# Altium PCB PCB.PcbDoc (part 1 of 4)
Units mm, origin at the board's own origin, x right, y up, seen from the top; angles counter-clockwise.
Board outline 114 x 86.5 mm, 4 copper layers (TOP, GND, SIG, BOTTOM), stack 1.586 mm thick; 98 components, 195 nets, 719 pads, 522 vias.
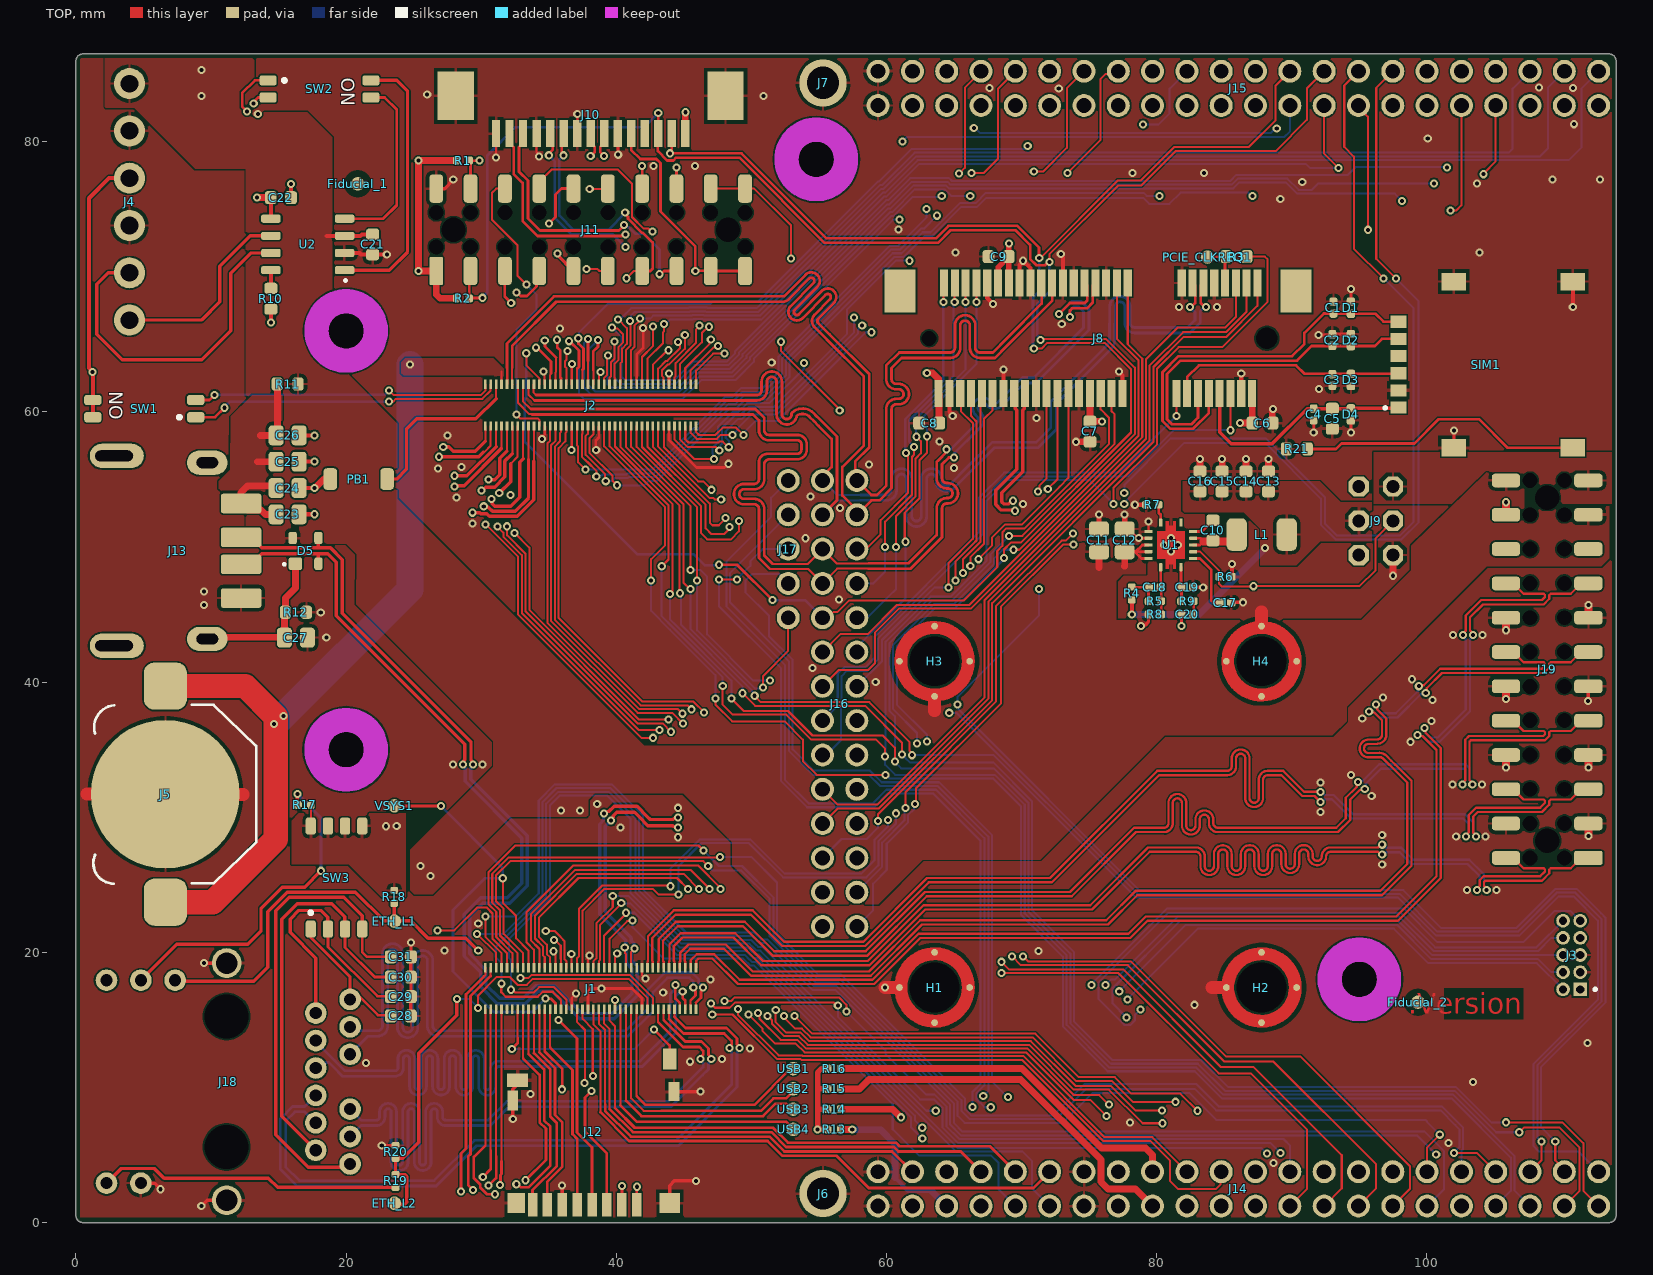
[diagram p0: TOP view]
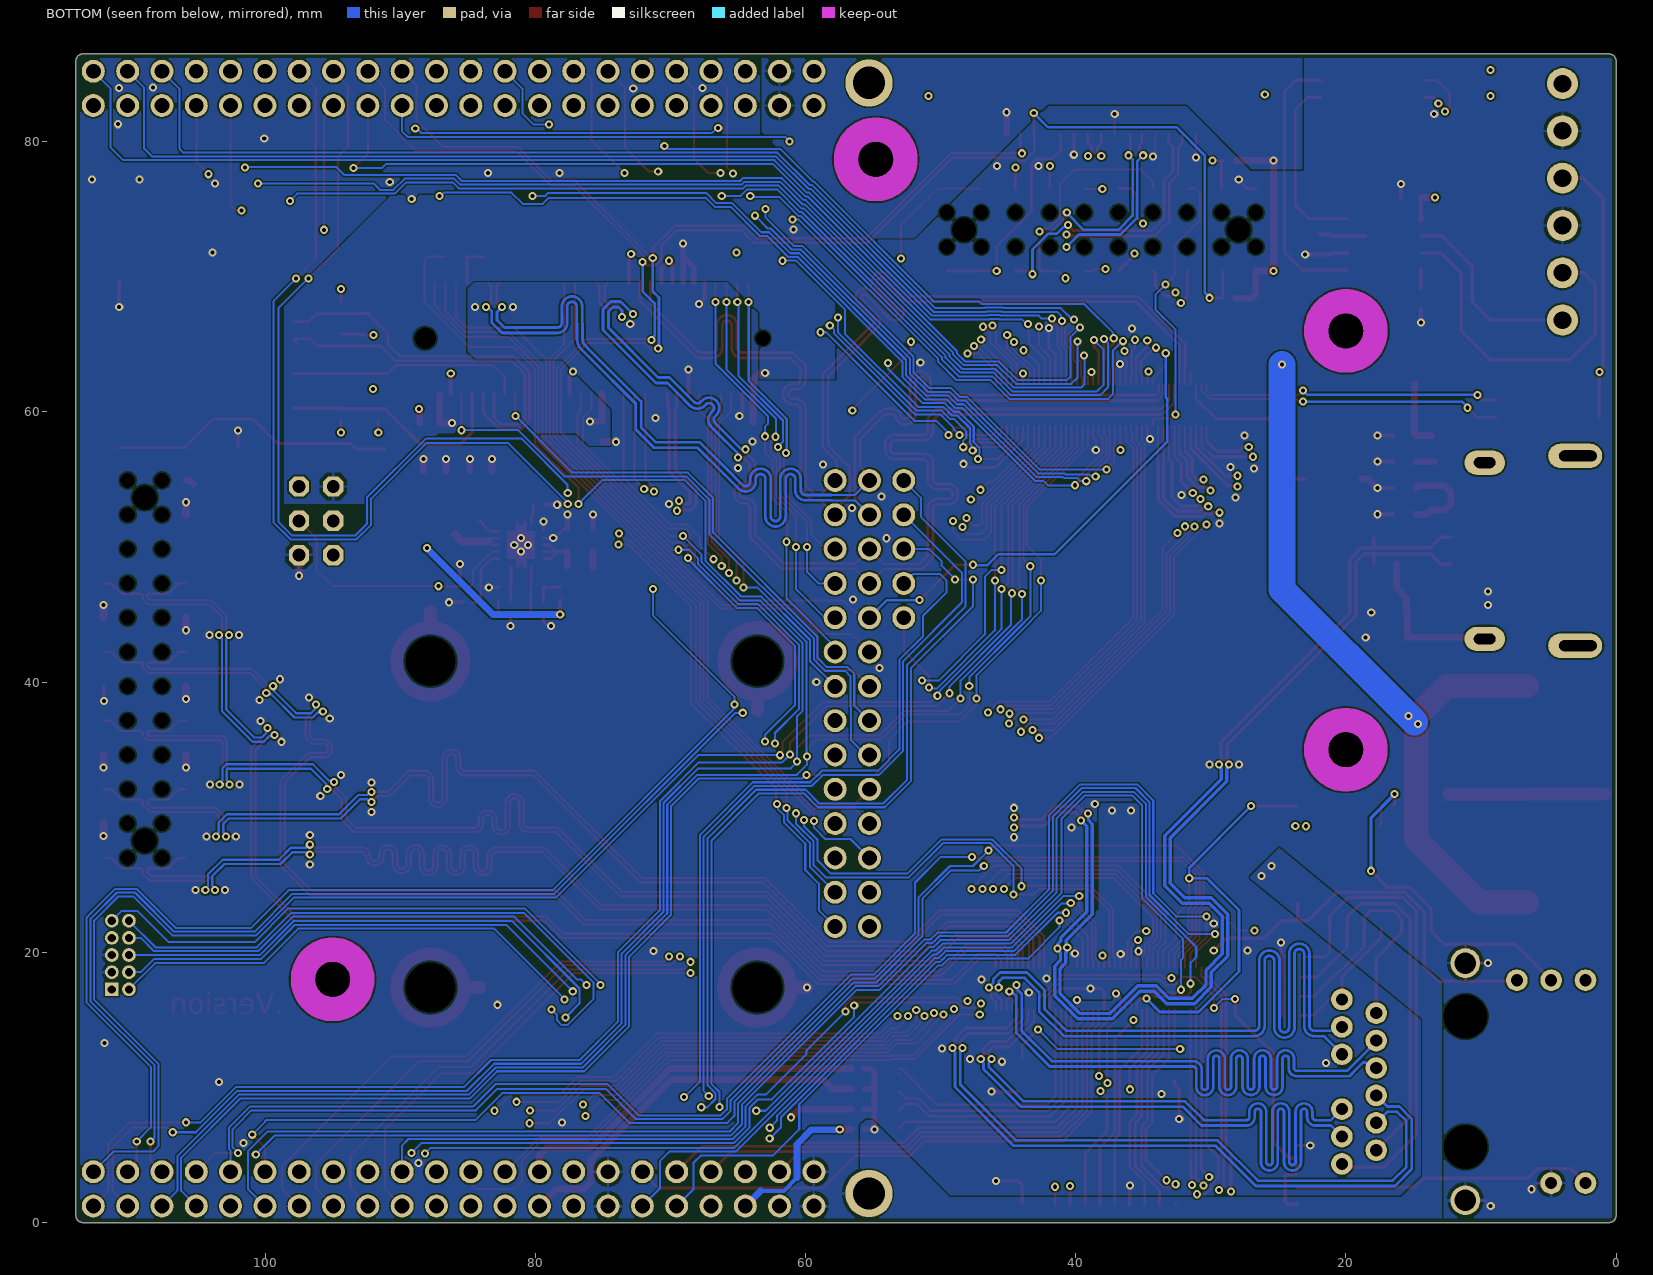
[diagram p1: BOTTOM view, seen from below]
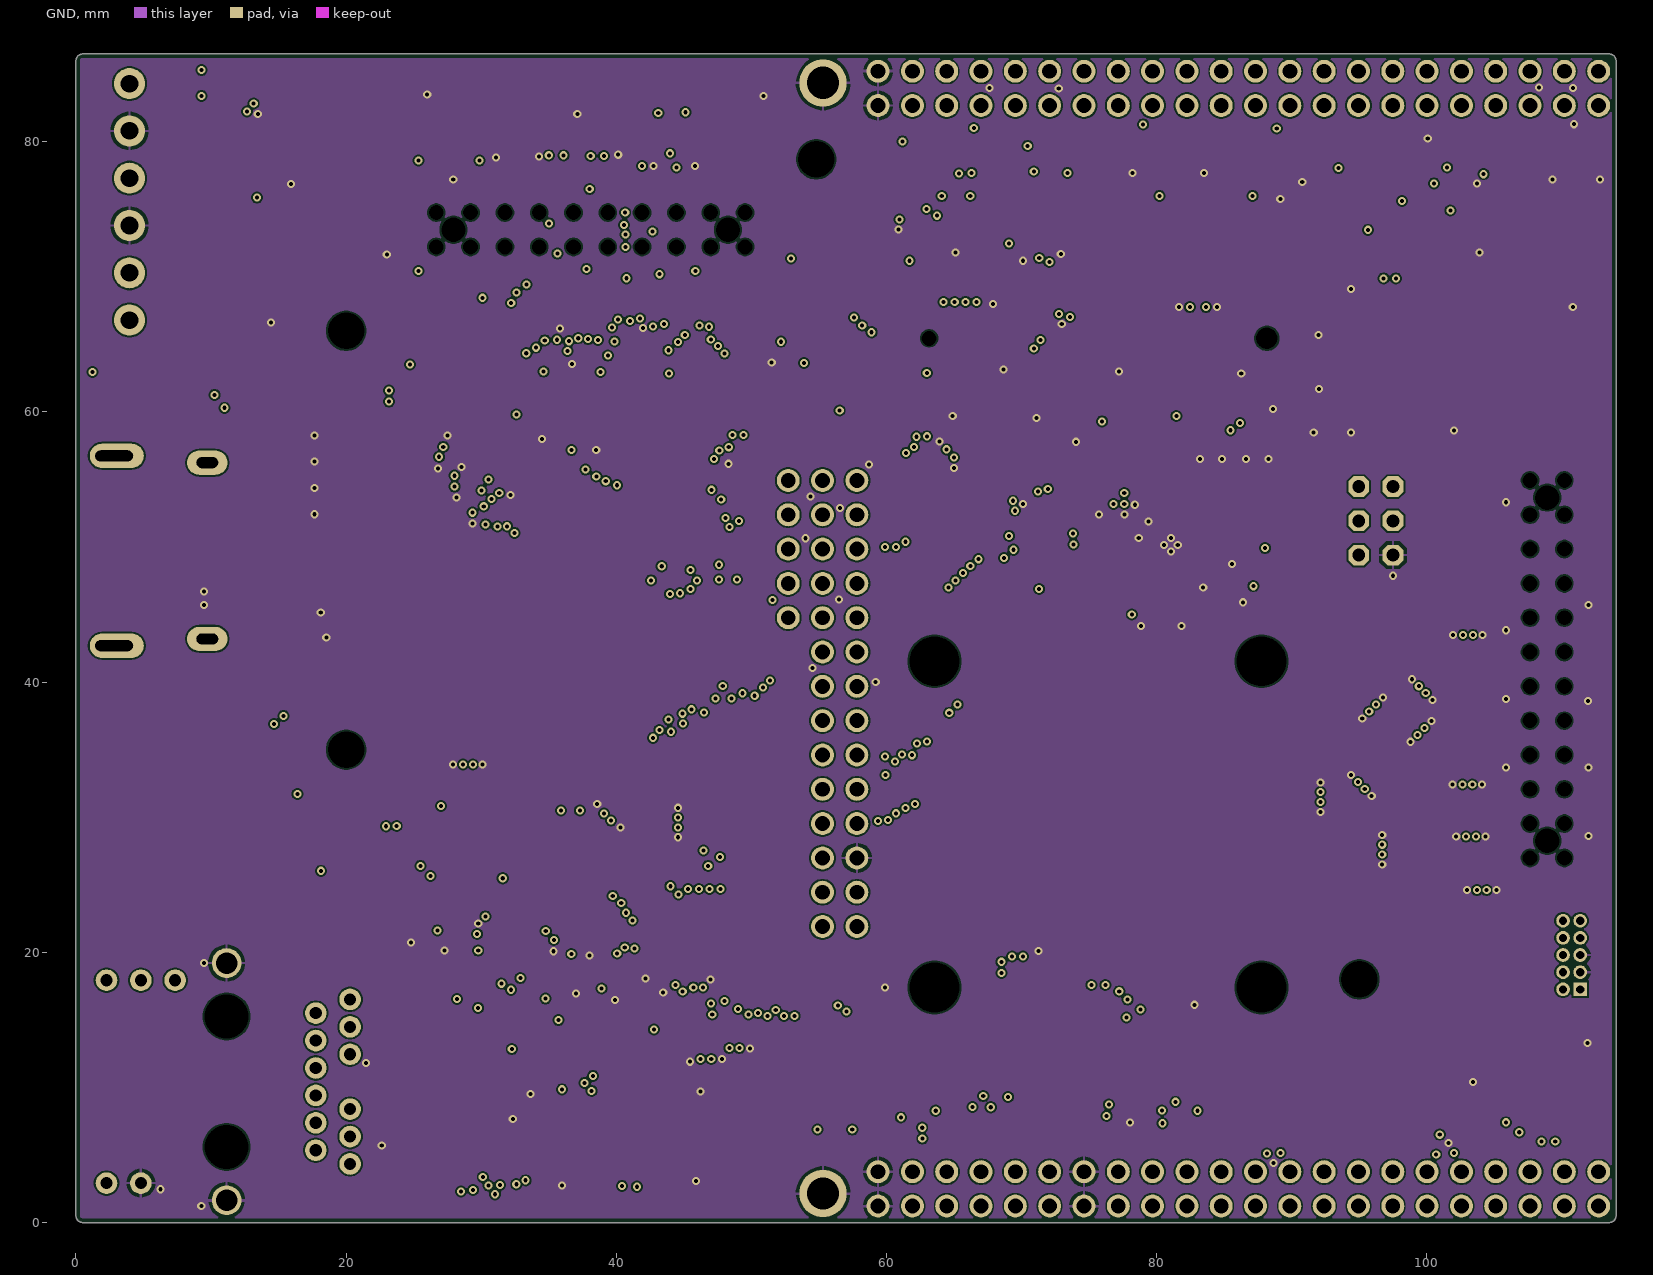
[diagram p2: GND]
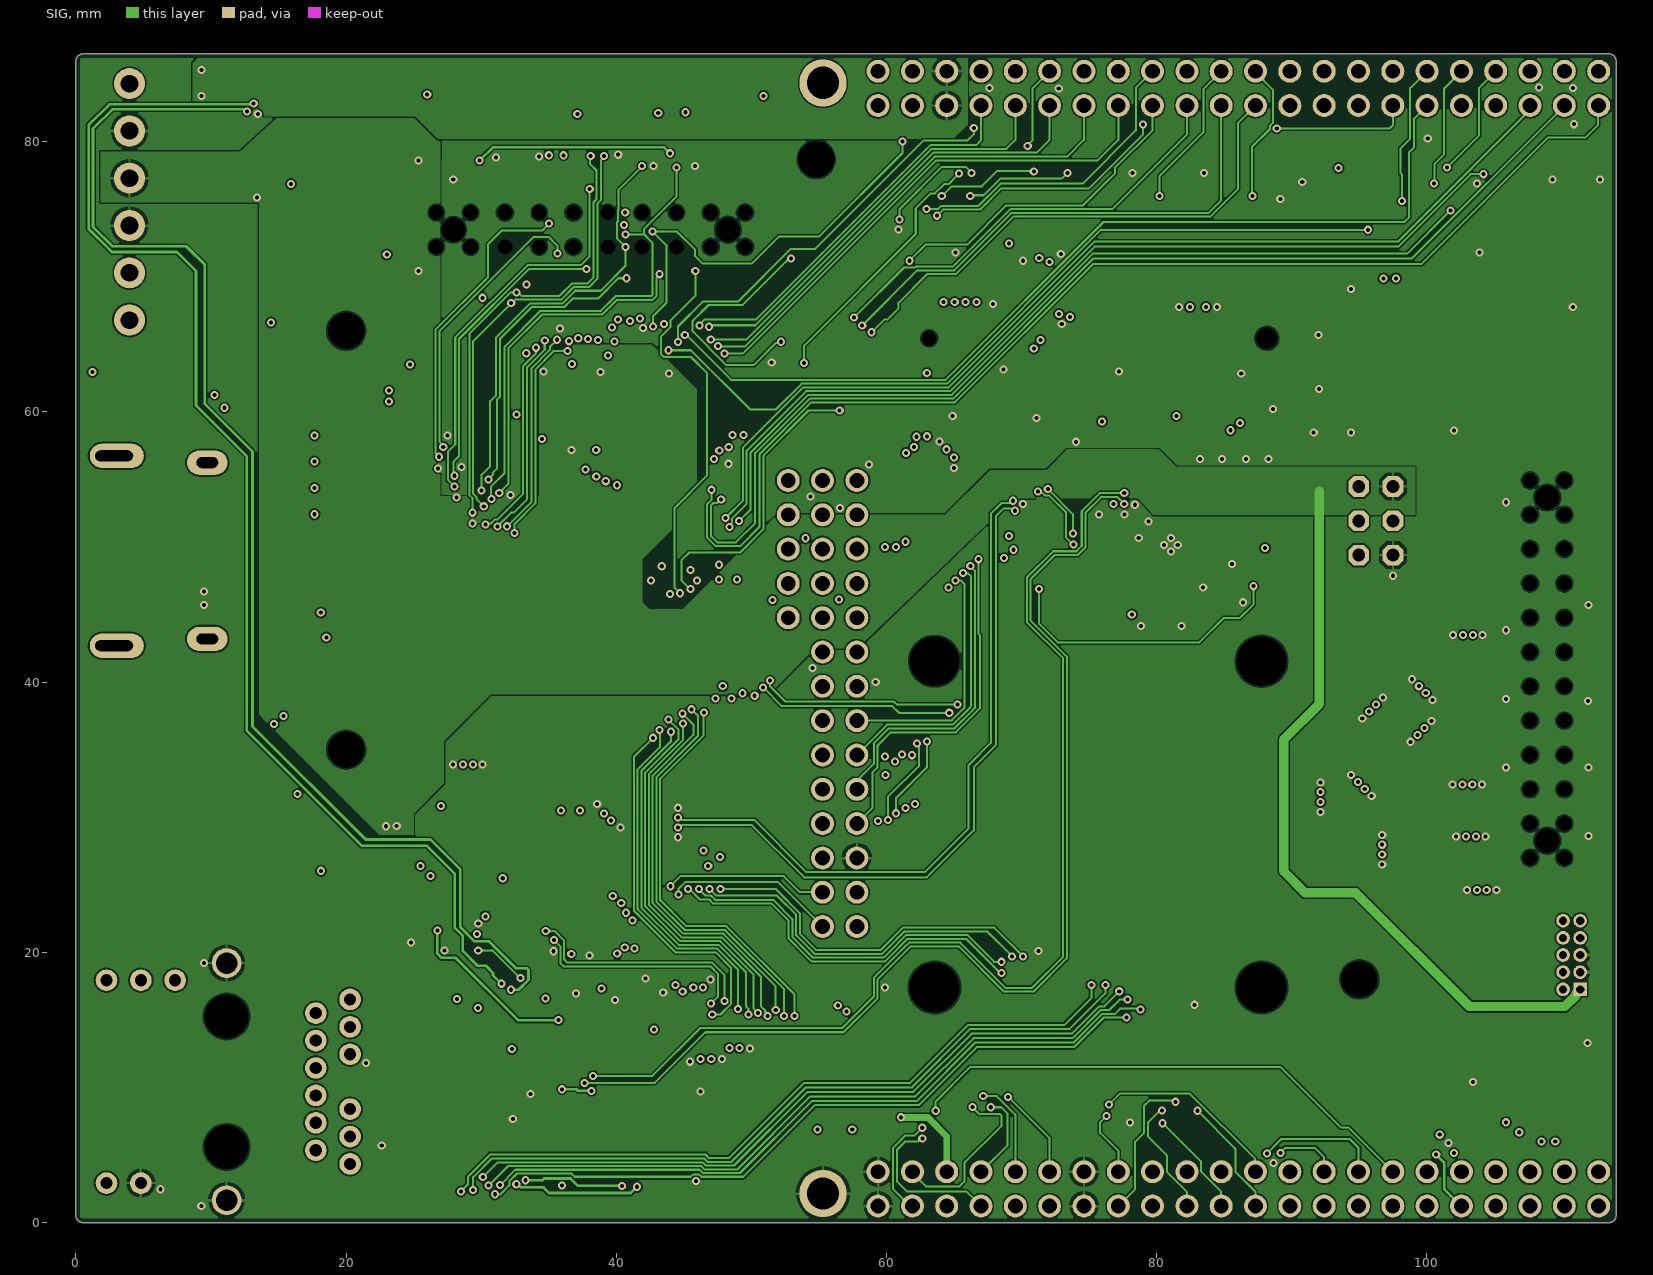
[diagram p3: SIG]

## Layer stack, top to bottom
Top Solder: solder mask 0.01, Solder Resist, Dk 3.5
TOP: signal copper 0.018
Dielectric 1: prepreg 0.14, PP-014, Dk 4.2
GND: signal copper 0.035
Dielectric2: core 1.2, FR-4, Dk 4.8
SIG: signal copper 0.035
Dielectric3: prepreg 0.14, PP-014, Dk 4.2
BOTTOM: signal copper 0.018
Bottom Solder: solder mask 0.01, Solder Resist, Dk 3.5

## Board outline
0.5,0 cw(c0.5,0.5) 0,0.5 0,86 cw(c0.5,86) 0.5,86.5 113.5,86.5 cw(c113.5,86) 114,86 114,0.5 cw(c113.5,0.5) 113.5,0

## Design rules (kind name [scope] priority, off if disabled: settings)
BoardOutlineClearance Silks [(OnLayer('Top Overlay') OR OnLayer('Bottom Overlay'))] p1: gap=0 ignorepadtopadclearanceinfootprint=FALSE
BoardOutlineClearance [All] p2: gap=0.3 ignorepadtopadclearanceinfootprint=FALSE
Clearance [All] p1: gap=0.127 ignorepadtopadclearanceinfootprint=TRUE
Clearance COPPER_0.3mm [All] p2: gap=0.127 ignorepadtopadclearanceinfootprint=TRUE except(0.3: Arc-Fill Arc-Poly Arc-Region Track-Fill Track-Poly Track-Region SMDPad-Fill SMDPad-Poly SMDPad-Region THPad-Fill THPad-Poly THPad-Region Via-Fill Via-Poly Via-Region Fill-Fill Fill-Poly Fill-Region Poly-Poly Poly-Region Region-Region)
Clearance COPPER_0.3mm_DIFF [InNetClass('DIFFERENTIAL')] p3: gap=0.127 ignorepadtopadclearanceinfootprint=TRUE except(0.3: Arc-Fill Arc-Poly Arc-Region Track-Fill Track-Poly Track-Region SMDPad-Fill SMDPad-Poly SMDPad-Region THPad-Fill THPad-Poly THPad-Region Via-Fill Via-Poly Via-Region Fill-Fill Fill-Poly Fill-Region Poly-Poly Poly-Region Region-Region)
Clearance "Generic clearance 0.127mm" [All] p4: gap=0.127 ignorepadtopadclearanceinfootprint=TRUE
ComponentClearance headers [InComponent('J17') vs InComponent('J16')] p1: gap=0 collisioncheckmode=3 verticalgap=0 showdistances=FALSE
ComponentClearance [All] p2: gap=0.2 collisioncheckmode=3 verticalgap=0 showdistances=TRUE
DiffPairsRouting USB [InDifferentialPairClass('USB')] p1: maxlimit=0.254 minlimit=0.15 mostfreqgap=0.254 toplayer_mingap=0.2 toplayer_maxgap=0.2 toplayer_prefgap=0.2 toplayer_minwidth=0.15 toplayer_maxwidth=0.25 toplayer_prefwidth=0.25 midlayer2_mingap=0.24 midlayer2_maxgap=0.24 midlayer2_prefgap=0.24 midlayer2_minwidth=0.15 midlayer2_maxwidth=0.15 midlayer2_prefwidth=0.15 bottomlayer_maxgap=0.15 bottomlayer_prefgap=0.15 bottomlayer_minwidth=0.25 bottomlayer_maxwidth=0.25 bottomlayer_prefwidth=0.25 impedanceprofiledriven=TRUE impedanceprofileid={E6B00C31-4C8E-439C-824F-D2B2CDC26F9C} impedanceprofilevalue=90.000000 maxuncoupledlength=12.7
DiffPairsRouting PCIE [InDifferentialPairClass('PCIE')] p2: maxlimit=0.2 minlimit=0.127 mostfreqgap=0.2 toplayer_mingap=0.2 toplayer_minwidth=0.15 toplayer_maxwidth=0.2 toplayer_prefwidth=0.2 midlayer1_maxgap=0.127 midlayer1_prefgap=0.127 midlayer1_minwidth=0.045 midlayer1_maxwidth=0.045 midlayer1_prefwidth=0.045 midlayer2_maxgap=0.127 midlayer2_prefgap=0.127 midlayer2_minwidth=0.045 midlayer2_maxwidth=0.045 midlayer2_prefwidth=0.045 bottomlayer_mingap=0.2 bottomlayer_minwidth=0.15 bottomlayer_maxwidth=0.2 bottomlayer_prefwidth=0.2 impedanceprofiledriven=TRUE impedanceprofileid={433C8B95-C78D-45E1-AD7A-F8BB8C5C9D6E} impedanceprofilevalue=100.000000 maxuncoupledlength=12.7
DiffPairsRouting DSI [InDifferentialPairClass('DSI')] p3: maxlimit=0.254 minlimit=0.15 mostfreqgap=0.254 toplayer_maxgap=0.15 toplayer_prefgap=0.15 toplayer_minwidth=0.17 toplayer_maxwidth=0.17 toplayer_prefwidth=0.17 bottomlayer_maxgap=0.15 bottomlayer_prefgap=0.15 bottomlayer_minwidth=0.17 bottomlayer_maxwidth=0.17 bottomlayer_prefwidth=0.17 impedanceprofiledriven=TRUE impedanceprofileid={B360A82F-7846-4579-ACC9-A6219EC6DBAC} impedanceprofilevalue=100.000000 maxuncoupledlength=12.7
DiffPairsRouting ETH [InDifferentialPairClass('ETH')] p4: maxlimit=0.2 minlimit=0.127 mostfreqgap=0.2 toplayer_mingap=0.2 toplayer_minwidth=0.15 toplayer_maxwidth=0.2 toplayer_prefwidth=0.2 midlayer1_maxgap=0.127 midlayer1_prefgap=0.127 midlayer1_minwidth=0.045 midlayer1_maxwidth=0.045 midlayer1_prefwidth=0.045 midlayer2_maxgap=0.127 midlayer2_prefgap=0.127 midlayer2_minwidth=0.045 midlayer2_maxwidth=0.045 midlayer2_prefwidth=0.045 bottomlayer_mingap=0.2 bottomlayer_minwidth=0.2 bottomlayer_maxwidth=0.2 bottomlayer_prefwidth=0.2 impedanceprofiledriven=TRUE impedanceprofileid={433C8B95-C78D-45E1-AD7A-F8BB8C5C9D6E} impedanceprofilevalue=100.000000 maxuncoupledlength=12.7
Height [All] p1: minheight=0 maxheight=30 prefheight=12.7
HoleSize [All] p1: absolutevalues=TRUE maxlimit=30 minlimit=0.3 maxpercent=80.000 minpercent=20.000
HoleToHoleClearance [All] p1: gap=0.25 allowstackedmicrovias=FALSE
MatchedLengths MatchedLengths_PCIE [InDifferentialPairClass('PCIE')] p1: tolerance=1.5 checknetsindiffpair=FALSE checkdiffpairvsdiffpair=TRUE checkxsignals=TRUE checkothers=TRUE usedelayunits=TRUE delaytolerance=30.000000
MatchedLengths MatchedLengths_ETH [InDifferentialPairClass('ETH')] p2: tolerance=1.5 checknetsindiffpair=FALSE checkdiffpairvsdiffpair=TRUE checkxsignals=TRUE checkothers=TRUE usedelayunits=TRUE delaytolerance=100.000000
MatchedLengths MatchedLengths_DSI [InDifferentialPairClass('DSI')] p3: tolerance=1.5 checknetsindiffpair=FALSE checkdiffpairvsdiffpair=TRUE checkxsignals=TRUE checkothers=TRUE usedelayunits=TRUE delaytolerance=30.000000
MinimumAnnularRing [All] p1: minimumring=0.15
PlaneConnect [All] p1: pad.planeconnectstyle=Relief pad.reliefexpansion=0.508 pad.reliefentries=4 pad.reliefconductorwidth=0.254 pad.reliefairgap=0.254 via.planeconnectstyle=Direct via.reliefexpansion=0.508 via.reliefentries=4 via.reliefconductorwidth=0.254 via.reliefairgap=0.254
PolygonConnect [All] p1: thpad.connectstyle=Relief thpad.reliefconductorwidth=0.2 thpad.reliefentries=4 thpad.polygonreliefangle="90 Angle" thpad.airgapwidth=0.254 smdpad.connectstyle=Relief smdpad.reliefconductorwidth=0.2 smdpad.reliefentries=4 smdpad.polygonreliefangle="90 Angle" smdpad.airgapwidth=0.254 via.connectstyle=Direct via.reliefconductorwidth=0.254 via.reliefentries=4 via.polygonreliefangle="90 Angle" via.airgapwidth=0.254
RoomDefinition TOP [InComponentClass('TOP')] p1: confinementstyle=ConfineIn formatcopy=TRUE lockcomponents=FALSE outline 121.82,0.96 177.7,0.96 177.7,16.2 121.82,16.2
RoutingVias StandardVias [All] p1: holewidth=0.3 width=0.6 viastyle="Through Hole" minholewidth=0.3 minwidth=0.6 maxholewidth=0.3 maxwidth=0.6
SMDToCorner [All] p1: distance=39370
SilkToSilkClearance [All] p1: silktosilkclearance=0.2
SilkToSolderMaskClearance [IsPad] p1: minsilkscreentomaskgap=0.15 clearancetoexposedcopper=TRUE
SolderMaskExpansion VIAtented [IsVia] p1: expansion=0.102 istentingtop=TRUE
SolderMaskExpansion [All] p2: expansion=0.05 istentingtop=FALSE
UnRoutedNet [All] p1: checkbadconnections=TRUE
ViasUnderSMD Buck_VIA [(ObjectKind = 'Pad') And (PadShape_AllLayers = 'Custom Shape') And (AsMM(PadXSize_AllLayers) = 3.5) And (AsMM(PadYSize_AllLayers) = 2.05)] p1: allowed=TRUE
ViasUnderSMD [All] p2: allowed=FALSE
Width StandardTraces [All] p1: maxlimit=5 minlimit=0.15 preferedwidth=0.15 minimp=50.000000 maximp=50.000000 favimp=50.000000
21 further rules are at their usual default settings.

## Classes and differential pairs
net class DIFFERENTIAL: CAM.CK_1_N CAM.CK_1_P CAM.D0_1_N CAM.D0_1_P CAM.D1_1_N CAM.D1_1_P CAM.D2_1_N CAM.D2_1_P CAM.D3_1_N CAM.D3_1_P CD CLK CMD D0 D1 D2 D3 DSI_CK_N DSI_CK_P DSI_D0_N DSI_D0_P DSI_D1_N DSI_D1_P DSI_D2_N DSI_D2_P DSI_D3_N DSI_D3_P ETH_A_N ETH_A_P ETH_B_N ETH_B_P ETH_C_N ETH_C_P ETH_D_N ETH_D_P mPCIe_CK_N mPCIe_CK_P mPCIe_RX_N mPCIe_RX_P mPCIe_TX_N mPCIe_TX_P USB0_D_N USB0_D_P USB1_D_N USB1_D_P
differential pair class DSI: DSI_CK DSI_D0 DSI_D1 DSI_D2 DSI_D3
differential pair class CAMERA: CAM.CK_1 CAM.D0_1 CAM.D1_1 CAM.D2_1 CAM.D3_1
component class U_USB: C23 C24 C25 C26 C27 D5 J13 R11 R12
differential pair class USB: USB0_D USB1.D_1 USB1_D
differential pair class PCIE: mPCIe_CK mPCIe_RX mPCIe_TX
differential pair class ETH: ETH_A ETH_B ETH_C ETH_D
net class SD: CD CLK CMD D0 D1 D2 D3
net class CAM: CAM.CK_1_N CAM.CK_1_P CAM.D0_1_N CAM.D0_1_P CAM.D1_1_N CAM.D1_1_P CAM.D2_1_P CAM.D3_1_P
component class U_SDcard: J12
component class U_MINI_PCIE: C1 C2 C3 C4 C5 C6 C7 C8 C9 C10 C11 C12 C13 C14 C15 C16 C17 C18 C19 C20 D1 D2 D3 D4 H1 H2 H3 H4 J8 J9 J16 J17 L1 PCIE_CLKREQ1 R3 R4 R5 R6 R7 R8 R9 R21 SIM1 U1
component class U_HEADERS: J14 J15 R13 R14 R15 R16
component class U_ETH: C28 C29 C30 C31 ETH_L1 ETH_L2 J18 R17 R18 R19 R20 SW3
component class U_DSI: J19
component class U_CAN_PHY: C21 C22 R10 U2
component class U_CAMERA: J10 J11
component class TOP: Fiducial_1 Fiducial_2 J3 J4 J5 J6 J7 PB1 R1 R2 SW1 SW2 USB1 USB2 USB3 USB4 VSYS1
component class "HDConnectors FEMALE": J1 J2
differential pair CAM.D3_1: +CAM.D3_1_P -CAM.D3_1_N
differential pair CAM.D2_1: +CAM.D2_1_P -CAM.D2_1_N
differential pair USB1_D: +USB1_D_P -USB1_D_N
differential pair mPCIe_RX: +mPCIe_RX_P -mPCIe_RX_N
differential pair mPCIe_CK: +mPCIe_CK_P -mPCIe_CK_N
differential pair DSI_D3: +DSI_D3_P -DSI_D3_N
differential pair DSI_D2: +DSI_D2_P -DSI_D2_N
differential pair DSI_D1: +DSI_D1_P -DSI_D1_N
differential pair DSI_D0: +DSI_D0_P -DSI_D0_N
differential pair DSI_CK: +DSI_CK_P -DSI_CK_N
differential pair CAM.D1_1: +CAM.D1_1_P -CAM.D1_1_N
differential pair CAM.D0_1: +CAM.D0_1_P -CAM.D0_1_N
differential pair CAM.CK_1: +CAM.CK_1_P -CAM.CK_1_N
differential pair USB0_D: +USB0_D_P -USB0_D_N
differential pair mPCIe_TX: +mPCIe_TX_P -mPCIe_TX_N
differential pair ETH_D: +ETH_D_P -ETH_D_N
differential pair ETH_C: +ETH_C_P -ETH_C_N
differential pair ETH_B: +ETH_B_P -ETH_B_N
differential pair ETH_A: +ETH_A_P -ETH_A_N

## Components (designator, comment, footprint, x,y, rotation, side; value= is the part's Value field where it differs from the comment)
C1 "CC0402JRNPO8BN470" CAP-0402 93.083,67.721 r270 top value=47pF
C2 "CC0402JRNPO8BN470" CAP-0402 93,65.321 r270 top value=47pF
C3 "CC0402JRNPO8BN470" CAP-0402 93,62.368 r90 top value=47pF
C4 "CC0402JRNPO8BN470" CAP-0402 91.622,59.815 r90 top value=47pF
C5 "0603B104K500CT" CAP-0603 93,59.5 r90 top value=100nF
C6 "GRM188R60J476ME15D" CAP-0603 87.826,59.176 r180 top value=47µF
C7 "GRM188R60J476ME15D" CAP-0603 75.056,58.554 r90 top value=47µF
C8 "GRM188R60J476ME15D" CAP-0603 63.156,59.176 r0 top value=47µF
C9 "0603B104K500CT" CAP-0603 68.296,71.5 r180 top value=100nF
C10 "0603B104K500CT" CAP-0603 84.163,51.234 r270 top value=100nF
C11 "CL21A226MAQNNNE" CAP-0805 75.724,50.491 r270 top value=22µF
C12 "CL21A226MAQNNNE" CAP-0805 77.627,50.491 r270 top value=22µF
C13 "GRM188R60J476ME15D" CAP-0603 88.275,54.86 r270 top value=47µF
C14 "GRM188R60J476ME15D" CAP-0603 86.608,54.86 r270 top value=47µF
C15 "GRM188R60J476ME15D" CAP-0603 84.842,54.86 r270 top value=47µF
C16 "GRM188R60J476ME15D" CAP-0603 83.205,54.86 r270 top value=47µF
C17 "C1005B103K500NT" CAP-0402 85.09,45.895 r0 top value=10nF
C18 "GRM1555C1H151FA01D" CAP-0402 79.864,47.025 r180 top value=150pF
C19 "C1005B103K500NT" CAP-0402 82.269,47.025 r180 top value=10nF
C20 "C1005B103K500NT" CAP-0402 82.269,45.013 r0 top value=10nF
C21 "0603B104K500CT" CAP-0603 21.964,72.4 r270 top value=100nF
C22 "0603B104K500CT" CAP-0603 15.167,75.866 r0 top value=100nF
C23 "CL21A226MAQNNNE" CAP-0805 15.664,52.418 r180 top value=22µF
C24 "CL21A226MAQNNNE" CAP-0805 15.664,54.368 r180 top value=22µF
C25 "CL21A226MAQNNNE" CAP-0805 15.664,56.318 r180 top value=22µF
C26 "CL21A226MAQNNNE" CAP-0805 15.664,58.268 r180 top value=22µF
C27 "FV21X472K102ECG" CAP-0805 16.28,43.3 r180 top value=4.7nF
C28 "0603B104K500CT" CAP-0603 24.045,15.288 r0 top value=100nF
C29 "0603B104K500CT" CAP-0603 24.05,16.723 r0 top value=100nF
C30 "0603B104K500CT" CAP-0603 24.045,18.167 r0 top value=100nF
C31 "0603B104K500CT" CAP-0603 24.05,19.669 r0 top value=100nF
D1 "PESD0402-140" 0402 94.376,67.721 r90 top
D2 "PESD0402-140" 0402 94.376,65.321 r90 top
D3 "PESD0402-140" 0402 94.376,62.368 r270 top
D4 "PESD0402-140" 0402 94.376,59.815 r270 top
D5 "PRTR5V0U2X,215" SOT190P230X110-4N 16.993,49.722 r0 top
ETH_L1 "Test point 1.00mm" TP-1.00MM 23.578,22.305 r90 top
ETH_L2 "Test point 1.00mm" TP-1.00MM 23.578,1.425 r180 top
Fiducial_1 "Fiducial mark 1mm with 2mm solder" "Fiducial mark 1mm with circle-Footprint-1" 20.857,76.885 r180 top
Fiducial_2 "Fiducial mark 1mm with 2mm solder" "Fiducial mark 1mm with circle-Footprint-1" 99.334,16.311 r180 top
H1 "9774070151R NO METAL IN HOLE" 9774070151R_HOLE_NO_METAL 63.556,17.397 r0 top
H2 "9774070151R NO METAL IN HOLE" 9774070151R_HOLE_NO_METAL 87.756,17.397 r0 top
H3 "9774070151R NO METAL IN HOLE" 9774070151R_HOLE_NO_METAL 63.556,41.547 r0 top
H4 "9774070151R NO METAL IN HOLE" 9774070151R_HOLE_NO_METAL 87.756,41.547 r0 top
J1 "DF40HC(4.0)-80DS-0.4V(51)-LEFT" DF40HC(4.0)-80DS-0.4V(51) 38.1,17.32 r180 top
J2 "DF40HC(4.0)-80DS-0.4V(51)-RIGHT" DF40HC(4.0)-80DS-0.4V(51) 38.1,60.5 r0 top
J3 "HPH2-A-10-SGA" PINHEAD_2X05_127 110.714,19.8 r180 top
J4 "22TW-277 6 PIN" "22TW-277 6 PIN" 3.962,75.553 r270 top
J5 "3000TR" 3000TR-Footprint-1 6.618,31.712 r90 top
J6 "1502-2" 1502-2 55.3,2.146 r0 top
J7 "1502-2" 1502-2 55.3,84.354 r0 top
J8 "1759546-1" 1759546-1 75.656,65.3 r180 top locked
J9 "PH2-06-UA" 2X03 96.22,51.941 r90 top
J10 "1-84953-5" 1-84952-5-Footprint-1 38.1,83.4 r180 top
J11 "21TW-247" 21TW-247 38.1,73.485 r0 top
J12 "114-00841-68" AMPHENOL_114-00841-68 38.3,7.2 r0 top
J13 "USB-A-S-RA-CS11-SMT-HF-TR" USB-A-S-RA-CS11-SMT-HF-TR 6.222,49.723 r270 top
J14 "61304421121" "PIN HEADER 2.54mm VERT. 2x22POS" 86.044,2.49 r0 top
J15 "61304421121" "PIN HEADER 2.54mm VERT. 2x22POS" 86.044,83.95 r0 top
J16 "PH2-28-UA" PH2-28-UA 56.534,38.419 r270 top
J17 "PH1-05-UA" PH1-05-UA 52.724,49.849 r270 top
J18 "TRJK7003A97NL" "TRJK0071AWNL -Footprint-2" 17.752,10.425 r270 top
J19 "21TW-291" 21TW-291 108.904,40.959 r90 top
L1 "SRP4020TA-3R3M" SRP4020 87.775,50.926 r0 top value=3.3µH
PB1 "IT-1185AP1C-160G-GTR" C&K_PTS820_NO_HOLES-1 20.929,55.035 r0 top
PCIE_CLKREQ1 "Test point 1.00mm" TP-1.00MM 83.759,71.47 r0 top
R1 "RC0402FR-075K1L" RES-0402 28.642,78.612 r180 top value=5.1k
R2 "RC0402FR-075K1L" RES-0402 28.642,68.411 r180 top value=5.1k
R3 "CRCW06030000Z0EAC" RES-0603 85.9,71.5 r180 top value=0
R4 "CRCW040249R9FKEDHP" RES-0402 78.155,46.571 r270 top value=49.9
R5 "CRCW040210K0FKED" RES-0402 79.864,45.994 r180 top value=10k
R6 "RC0402FR-075K1L" RES-0402 85.09,47.8 r180 top value=5.1k
R7 "CRCW040275K0FKED" RES-0402 79.674,53.127 r0 top value=75k
R8 "RC0402FR-073K3L" RES-0402 79.864,45.013 r0 top value=3.3k
R9 "RC0402FR-0734KL" RES-0402 82.269,45.994 r180 top value=34k
R10 "CRCW060375K0FKEAC" RES-0603 14.43,68.381 r90 top value=75k
R11 "CRCW06030000Z0EAC" RES-0603 15.664,62.068 r180 top value=0
R12 "CRCW06031M00FKEA" RES-0603 16.28,45.173 r180 top value=1M
R13 "RC0402FR-073K3L" RES-0402 56.118,6.892 r180 top value=3.3k
R14 "RC0402FR-073K3L" RES-0402 56.118,8.392 r0 top value=3.3k
R15 "RC0402FR-073K3L" RES-0402 56.118,9.892 r180 top value=3.3k
R16 "RC0402FR-073K3L" RES-0402 56.118,11.392 r0 top value=3.3k
R17 "CRCW0402470RJNED" RES-0402 16.92,30.91 r0 top value=470
R18 "CRCW040210K0FKED" RES-0402 23.556,24.102 r90 top value=10k
R19 "CRCW0402470RJNED" RES-0402 23.657,3.079 r90 top value=470
R20 "CRCW040210K0FKED" RES-0402 23.657,5.229 r90 top value=10k
R21 "CRCW06030000Z0EAC" RES-0603 90.376,57.265 r0 top value=0
SIM1 "SIM8060-6-1-14-00-A" SIM8060-6-0-14-00-A-Footprint-1 105.214,63.5 r90 top
SW1 "218-2LPSTRF" CTS-218-2LPST_V 5.055,60.247 r180 top
SW2 "218-2LPSTRF" CTS-218-2LPST_V 18.027,83.909 r0 top
SW3 "218-4LPSTRF" CTS-218-4LPST_V 19.284,25.536 r90 top
U1 "TPS54620RGYR" RHL0014A_V 81.049,50.159 r0 top
U2 "TJA1049T/3J" TJA1049T_3J-Footprint-1 17.157,72.4 r180 top
USB1 "Test point 1.00mm" TP-1.00MM 53.098,11.392 r90 top
USB2 "Test point 1.00mm" TP-1.00MM 53.098,9.892 r90 top
USB3 "Test point 1.00mm" TP-1.00MM 53.098,8.392 r90 top
USB4 "Test point 1.00mm" TP-1.00MM 53.098,6.892 r90 top
VSYS1 "Test point 1.00mm" TP-1.00MM 23.578,30.848 r90 top

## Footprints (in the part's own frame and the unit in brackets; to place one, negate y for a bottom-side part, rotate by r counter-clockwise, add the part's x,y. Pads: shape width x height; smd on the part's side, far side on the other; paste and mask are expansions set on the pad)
1-84952-5-Footprint-1 [mm]
  rect 0.61x2 smd mask+0.05: 1(7,2.8) 2(6,2.8) 3(5,2.8) 4(4,2.8) 5(3,2.8) 6(2,2.8) 7(1,2.8) 8(0,2.8) 9(-1,2.8) 10(-2,2.8) 11(-3,2.8) 12(-4,2.8) 13(-5,2.8) 14(-6,2.8) 15(-7,2.8)
  rect 2.68x3.6 smd mask+0.05: FIX(-9.99,0) FIX(9.99,0)
  body extent -11.46,-3.64 11.46,2.9, height 2.59
2X03 [mm]
  oct 1.501x1.501 / inner oct 1.524x1.524 / far side oct 1.501x1.501 hole 0.95: 1(2.54,1.27) 2(2.54,-1.27) 3(0,1.27) 4(0,-1.27) 5(-2.54,1.27) 6(-2.54,-1.27)
  body extent -3.81,-2.54 3.81,2.5, height 8.5
21TW-247 [mm]
  round 0 hole 1.1 unplated mask+0.2: 0(-11.43,-1.27) 0(-11.43,1.27) 0(-8.89,-1.27) 0(-8.89,1.27) 0(-6.35,-1.27) 0(-6.35,1.27) 0(-3.81,-1.27) 0(-3.81,1.27) 0(-1.27,-1.27) 0(-1.27,1.27) 0(1.27,1.27) 0(1.27,-1.27) 0(3.81,-1.27) 0(3.81,1.27) 0(6.35,-1.27) 0(6.35,1.27) 0(8.89,-1.27) 0(8.89,1.27) 0(11.43,-1.27) 0(11.43,1.27)
  round 0 hole 1.8 unplated paste-2539.97: 0(-10.16,0) 0(10.16,0)
  rrect25% 1.02x2.1 smd mask+0.1: 1(-11.43,-3.05)
  rrect50% 1.02x2.1 smd mask+0.1: 2(-11.43,3.05) 3(-8.89,-3.05) 4(-8.89,3.05) 5(-6.35,-3.05) 6(-6.35,3.05) 7(-3.81,-3.05) 8(-3.81,3.05) 9(-1.27,-3.05) 10(-1.27,3.05) 11(1.27,-3.05) 12(1.27,3.05) 13(3.81,-3.05) 14(3.81,3.05) 15(6.35,-3.05) 16(6.35,3.05) 17(8.89,-3.05) 18(8.89,3.05) 19(11.43,-3.05) 20(11.43,3.05)
  body extent -12.7,-3.29 12.7,3.29, height 3.71
21TW-291 [mm]
  round 0 hole 1.1 unplated mask+0.2: 0(-13.97,-1.27) 0(-13.97,1.27) 0(-11.43,-1.27) 0(-11.43,1.27) 0(-8.89,-1.27) 0(-8.89,1.27) 0(-6.35,-1.27) 0(-6.35,1.27) 0(-3.81,-1.27) 0(-3.81,1.27) 0(-1.27,-1.27) 0(-1.27,1.27) 0(1.27,-1.27) 0(1.27,1.27) 0(3.81,-1.27) 0(3.81,1.27) 0(6.35,-1.27) 0(6.35,1.27) 0(8.89,-1.27) 0(8.89,1.27) 0(11.43,-1.27) 0(11.43,1.27) 0(13.97,-1.27) 0(13.97,1.27)
  round 0 hole 1.8 unplated paste-2539.97: 0(-12.7,0) 0(12.7,0)
  rrect25% 1.02x2.1 smd mask+0.1: 1(-13.97,-3.05)
  rrect50% 1.02x2.1 smd mask+0.1: 2(-13.97,3.05) 3(-11.43,-3.05) 4(-11.43,3.05) 5(-8.89,-3.05) 6(-8.89,3.05) 7(-6.35,-3.05) 8(-6.35,3.05) 9(-3.81,-3.05) 10(-3.81,3.05) 11(-1.27,-3.05) 12(-1.27,3.05) 13(1.27,-3.05) 14(1.27,3.05) 15(3.81,-3.05) 16(3.81,3.05) 17(6.35,-3.05) 18(6.35,3.05) 19(8.89,-3.05) 20(8.89,3.05) 21(11.43,-3.05) 22(11.43,3.05) 23(13.97,-3.05) 24(13.97,3.05)
  body extent -15.27,-3.29 15.21,3.29, height 3.71
"22TW-277 6 PIN" [mm]
  round 2.3 hole 1.3: 1(-8.75,0) 2(-5.25,0) 3(-1.75,0) 4(1.75,0) 5(5.25,0) 6(8.75,0)
  body extent -10.98,-3.75 11,3.25, height 8.31
0402 [mm] "Chip Resistor, 2-Leads, Body  0402 (in) 1005 (mm), IPC Medium Density"
  rrect50% 0.62x0.62 smd mask+0.05: A(0.45,0) C(-0.45,0)
  body extent -0.5,-0.3 0.5,0.3, height 0.5
1502-2 [mm]
  round 3.5 hole 2.4 paste-2539.97 mask+0.102: 1(0,0)
  body extent -1.58,-1.59 1.58,1.59, height 5.63
3000TR-Footprint-1 [mm] "Default PCB Component"
  rrect50% 3.5x3.2 smd paste-0.3: 1(-8,0) 2(8,0)
  round 11 smd paste-3.5: 3(0,0)
  silkscreen extent -6.62,-6.73 6.61,5.33, body extent -9.46,-6.91 9.49,5.15, height 3.2
1759546-1 [mm]
  rect 0.6x2 smd mask+0: 1(-11.8,-4.25) 2(-11.4,3.95) 3(-11,-4.25) 4(-10.6,3.95) 5(-10.2,-4.25) 6(-9.8,3.95) 7(-9.4,-4.25) 8(-9,3.95) 9(-8.6,-4.25) 10(-8.2,3.95) 11(-7.8,-4.25) 12(-7.4,3.95) 13(-7,-4.25) 14(-6.6,3.95) 15(-6.2,-4.25) 16(-5.8,3.95) 17(-2.2,-4.25) 18(-1.8,3.95) 19(-1.4,-4.25) 20(-1,3.95) 21(-0.6,-4.25) 22(-0.2,3.95) 23(0.2,-4.25) 24(0.6,3.95) 25(1,-4.25) 26(1.4,3.95) 27(1.8,-4.25) 28(2.2,3.95) 29(2.6,-4.25) 30(3,3.95) 31(3.4,-4.25) 32(3.8,3.95) 33(4.2,-4.25) 34(4.6,3.95) 35(5,-4.25) 36(5.4,3.95) 37(5.8,-4.25) 38(6.2,3.95) 39(6.6,-4.25) 40(7,3.95) 41(7.4,-4.25) 42(7.8,3.95) 43(8.2,-4.25) 44(8.6,3.95) 45(9,-4.25) 46(9.4,3.95) 47(9.8,-4.25) 48(10.2,3.95) 49(10.6,-4.25) 50(11,3.95) 51(11.4,-4.25) 52(11.8,3.95)
  round 0 hole 1.6 unplated: MH1(-12.5,-0.15)
  round 0 hole 1.1 unplated: MH2(12.5,-0.15)
  rect 2.3x3.2 smd: MP1(-14.65,-3.65) MP2(14.65,-3.65)
  body extent -15,-4.56 15,4.7, height 9.92
9774070151R_HOLE_NO_METAL [mm]
  round 1 hole 3.7 unplated paste-2539.97 mask+0.1: 0(0,0)
  round 0.5 smd paste-10: 1(-2.6,0) 1(0,-2.6) 1(0,2.6) 1(2.6,0)
  TOP circle w0.95: c0,0 r2.5
  TOP pour cut-out: 0,3.3 1.263,3.049 2.333,2.333 3.049,1.263 3.3,0 3.3,0 3.049,-1.263 2.333,-2.333 1.263,-3.049 0,-3.3 0,-3.3 -1.263,-3.049 -2.333,-2.333 -3.049,-1.263 -3.3,0 -3.3,0 -3.049,1.263 -2.333,2.333 -1.263,3.049 0,3.3
AMPHENOL_114-00841-68 [mm]
  rect 0.7x1.75 smd mask+0.05: 1(3.2,-5.888) 2(2.1,-5.888) 3(1,-5.888) 4(-0.1,-5.888) 5(-1.2,-5.888) 6(-2.3,-5.888) 7(-3.4,-5.888) 8(-4.5,-5.888)
  rect 1x1.55 smd mask+0.05: CD1(5.65,4.912)
  rect 1.55x1 smd mask+0.05: CD2(-5.602,3.337)
  rect 1.3x1.5 smd mask+0: SH1(-5.7,-5.76)
  rect 1.5x1.5 smd mask+0: SH2(5.65,-5.76)
  rect 0.8x1.4 smd mask+0.05: SH3(5.975,2.487)
  rect 0.8x1.5 smd mask+0.05: SH4(-5.975,1.837)
  body extent -6,-10.29 6,4.99, height 1.6
C&K_PTS820_NO_HOLES-1 [mm]
  rrect49% 1x1.6 smd mask+0.05: 1(-2.1,0) 2(2.1,0)
  body extent -2.25,-1.45 2.25,1.45, height 2
CAP-0402 [mm] "Chip Capacitor, 2-Leads, Body  0402 (in) 1005 (mm), IPC Medium Density"
  rrect52% 0.63x0.58 smd mask+0.05: 1(-0.435,0) 2(0.435,0)
  body extent -0.5,-0.25 0.5,0.25, height 0.5
CAP-0603 [mm] "Chip Capacitor, Body 0603 imperial,1.6x0.8mm, IPC High Density"
  rrect51% 0.87x0.97 smd mask+0.05: 1(-0.75,0) 2(0.75,0)
  body extent -0.8,-0.4 0.8,0.4, height 0.8
CAP-0805 [mm] "Chip Capacitor, Body 0805 imperial, 2.0x1.2mm, IPC Medium Density"
  rrect45% 1.11x1.47 smd mask+0.05: 1(-0.85,0) 2(0.85,0)
  body extent -1,-0.62 1,0.63, height 1.25
CTS-218-2LPST_V [mm] "SMD, 4-Leads, Body 5.8x3.71mm, Pitch 1.27mm"
  rrect50% 1.27x0.76 smd: 1(-3.81,0.635) 2(-3.81,-0.635) 3(3.81,-0.635) 4(3.81,0.635)
  silkscreen extent -2.7,0.54 -2.5,0.73, body extent -4.22,-1.85 4.22,1.86, height 2.5
CTS-218-4LPST_V [mm] "SMD, 8-Leads, Body 5.8x6.25mm, Pitch 1.27mm"
  rrect50% 1.27x0.76 smd: 1(-3.81,1.905) 2(-3.81,0.635) 3(-3.81,-0.635) 4(-3.81,-1.905) 5(3.81,-1.905) 6(3.81,-0.635) 7(3.81,0.635) 8(3.81,1.905)
  silkscreen extent -2.7,1.81 -2.5,2, body extent -4.22,-3.13 4.22,3.13, height 2.59
DF40HC(4.0)-80DS-0.4V(51) [mm]
  rect 0.2x0.7 smd mask+0: 1(-7.8,1.54) 2(-7.8,-1.54) 3(-7.4,1.54) 4(-7.4,-1.54) 5(-7,1.54) 6(-7,-1.54) 7(-6.6,1.54) 8(-6.6,-1.54) 9(-6.2,1.54) 10(-6.2,-1.54) 11(-5.8,1.54) 12(-5.8,-1.54) 13(-5.4,1.54) 14(-5.4,-1.54) 15(-5,1.54) 16(-5,-1.54) 17(-4.6,1.54) 18(-4.6,-1.54) 19(-4.2,1.54) 20(-4.2,-1.54) 21(-3.8,1.54) 22(-3.8,-1.54) 23(-3.4,1.54) 24(-3.4,-1.54) 25(-3,1.54) 26(-3,-1.54) 27(-2.6,1.54) 28(-2.6,-1.54) 29(-2.2,1.54) 30(-2.2,-1.54) 31(-1.8,1.54) 32(-1.8,-1.54) 33(-1.4,1.54) 34(-1.4,-1.54) 35(-1,1.54) 36(-1,-1.54) 37(-0.6,1.54) 38(-0.6,-1.54) 39(-0.2,1.54) 40(-0.2,-1.54) 41(0.2,1.54) 42(0.2,-1.54) 43(0.6,1.54) 44(0.6,-1.54) 45(1,1.54) 46(1,-1.54) 47(1.4,1.54) 48(1.4,-1.54) 49(1.8,1.54) 50(1.8,-1.54) 51(2.2,1.54) 52(2.2,-1.54) 53(2.6,1.54) 54(2.6,-1.54) 55(3,1.54) 56(3,-1.54) 57(3.4,1.54) 58(3.4,-1.54) 59(3.8,1.54) 60(3.8,-1.54) 61(4.2,1.54) 62(4.2,-1.54) 63(4.6,1.54) 64(4.6,-1.54) 65(5,1.54) 66(5,-1.54) 67(5.4,1.54) 68(5.4,-1.54) 69(5.8,1.54) 70(5.8,-1.54) 71(6.2,1.54) 72(6.2,-1.54) 73(6.6,1.54) 74(6.6,-1.54) 75(7,1.54) 76(7,-1.54) 77(7.4,1.54) 78(7.4,-1.54) 79(7.8,1.54) 80(7.8,-1.54)
  body extent -9.3,-1.69 9.3,1.69, height 3.89
"Fiducial mark 1mm with circle-Footprint-1" [mm]
  round 1 smd paste-10 mask+0.5: 1(0,0)
  TOP pour cut-out: 0,1 0.383,0.924 0.707,0.707 0.924,0.383 1,0 1,0 0.924,-0.383 0.707,-0.707 0.383,-0.924 0,-1 0,-1 -0.383,-0.924 -0.707,-0.707 -0.924,-0.383 -1,0 -1,0 -0.924,0.383 -0.707,0.707 -0.383,0.924 0,1
PH1-05-UA [mm]
  round 1.7 hole 1.1 mask+0.1: 1(-5.08,0) 2(-2.54,0) 3(0,0) 4(2.54,0) 5(5.08,0)
  body extent -6.35,-1.27 6.35,1.27, height 9.5
PH2-28-UA [mm]
  round 1.7 hole 1.1 mask+0.1: 1(-16.51,-1.27) 2(-16.51,1.27) 3(-13.97,-1.27) 4(-13.97,1.27) 5(-11.43,-1.27) 6(-11.43,1.27) 7(-8.89,-1.27) 8(-8.89,1.27) 9(-6.35,-1.27) 10(-6.35,1.27) 11(-3.81,-1.27) 12(-3.81,1.27) 13(-1.27,-1.27) 14(-1.27,1.27) 15(1.27,-1.27) 16(1.27,1.27) 17(3.81,-1.27) 18(3.81,1.27) 19(6.35,-1.27) 20(6.35,1.27) 21(8.89,-1.27) 22(8.89,1.27) 23(11.43,-1.27) 24(11.43,1.27) 25(13.97,-1.27) 26(13.97,1.27) 27(16.51,-1.27) 28(16.51,1.27)
  body extent -17.78,-2.54 17.78,2.54, height 9.5
"PIN HEADER 2.54mm VERT. 2x22POS" [mm]
  round 1.7 hole 1.1 mask+0.1: 1(-26.67,-1.27) 2(-26.67,1.27) 3(-24.13,-1.27) 4(-24.13,1.27) 5(-21.59,-1.27) 6(-21.59,1.27) 7(-19.05,-1.27) 8(-19.05,1.27) 9(-16.51,-1.27) 10(-16.51,1.27) 11(-13.97,-1.27) 12(-13.97,1.27) 13(-11.43,-1.27) 14(-11.43,1.27) 15(-8.89,-1.27) 16(-8.89,1.27) 17(-6.35,-1.27) 18(-6.35,1.27) 19(-3.81,-1.27) 20(-3.81,1.27) 21(-1.27,-1.27) 22(-1.27,1.27) 23(1.27,-1.27) 24(1.27,1.27) 25(3.81,-1.27) 26(3.81,1.27) 27(6.35,-1.27) 28(6.35,1.27) 29(8.89,-1.27) 30(8.89,1.27) 31(11.43,-1.27) 32(11.43,1.27) 33(13.97,-1.27) 34(13.97,1.27) 35(16.51,-1.27) 36(16.51,1.27) 37(19.05,-1.27) 38(19.05,1.27) 39(21.59,-1.27) 40(21.59,1.27) 41(24.13,-1.27) 42(24.13,1.27) 43(26.67,-1.27) 44(26.67,1.27)
  body extent -27.94,-2.54 27.94,2.54, height 9.5
PINHEAD_2X05_127 [mil]
  rect 38.73x38.73 / inner rect 38.74x38.74 / far side rect 38.73x38.73 hole 23.62: 1(-25,100)
  round 40 hole 23.62: 2(25,100) 3(-25,50) 4(25,50) 5(-25,0) 6(25,0) 7(-25,-50) 8(25,-50) 9(-25,-100) 10(25,-100)
  silkscreen extent -70,98 -67,102, body extent -68,-125 68,125, height 158
RES-0402 [mm] "Chip Resistor, 2-Leads, Body  0402 (in) 1005 (mm), IPC Medium Density"
  rrect51% 0.55x0.58 smd mask+0.05: 1(-0.475,0) 2(0.475,0)
  body extent -0.5,-0.25 0.5,0.25, height 0.34
RES-0603 [mm] "Chip Resistor - Body 0603 imperial,1.6x0.8mm, IPC High Density"
  rrect51% 0.82x0.97 smd mask+0.05: 1(-0.775,0) 2(0.775,0)
  body extent -0.8,-0.4 0.8,0.4, height 0.43
RHL0014A_V [mm] "QFN, 14-Leads, Body 3.5x3.5mm, Pitch 0.5mm, Thermal Pad 2.05x2.05mm, TI Recommended"
  rrect42% 0.24x0.6 smd mask+0.05: 1(-0.75,1.65) 7(-0.75,-1.65) 8(0.75,-1.65) 14(0.75,1.65)
  rrect42% 0.6x0.24 smd mask+0.05: 2(-1.65,1) 3(-1.65,0.5) 4(-1.65,0) 5(-1.65,-0.5) 6(-1.65,-1) 9(1.65,-1) 10(1.65,-0.5) 11(1.65,0) 12(1.65,0.5) 13(1.65,1)
  round 0.025 smd paste-2539.97 mask+0.05: 15(0,0)
  TOP region: -0.974,1.025 -0.375,1.025 -0.375,1.75 -0.175,1.75 -0.175,1.425 0.175,1.425 0.175,1.75 0.375,1.75 0.375,1.025 0.974,1.025 0.993,1.021 1.01,1.01 1.021,0.993 1.025,0.974 1.025,0.974 1.025,-0.974 1.021,-0.993 1.01,-1.01 0.993,-1.021 0.974,-1.025 0.974,-1.025 0.375,-1.025 0.375,-1.75 0.175,-1.75 0.175,-1.426 -0.175,-1.425 -0.175,-1.75 -0.375,-1.75 -0.375,-1.025 -0.974,-1.025 -0.994,-1.021 -1.01,-1.01 -1.021,-0.993 -1.025,-0.974 -1.025,-0.974 -1.025,0.974 -1.021,0.993 -1.01,1.01 -0.994,1.021 -0.974,1.025
  body extent -1.68,-1.83 1.68,1.82, height 1
SIM8060-6-0-14-00-A-Footprint-1 [mm]
  rect 0.9x1.2 smd: C1(-3.17,7.32) C2(-0.63,7.32) C3(1.91,7.32) C5(-1.9,7.32) C6(0.64,7.32) C7(3.18,7.32)
  rect 1.3x1.8 smd: G1(-6.15,3.22) G2(6.15,3.22) G3(-6.15,-5.58) G4(6.15,-5.58)
  silkscreen extent -3.3,8.2 -3.1,8.4, body extent -6.67,-7.92 6.67,7.83, height 1.53
SOT190P230X110-4N [mm]
  rrect33% 1.01x0.91 smd paste+0 mask+0.05: 1(-0.75,-0.955)
  rrect49% 0.61x0.91 smd paste+0 mask+0.05: 2(0.95,-0.955) 3(0.95,0.955) 4(-0.95,0.955)
  silkscreen extent -1.62,-1.05 -1.52,-0.95, body extent -1.45,-1.15 1.45,1.15, height 1
SRP4020 [mm]
  rrect50% 1.5x2.4 smd: 1(-1.85,0) 2(1.85,0)
  body extent -2.7,-2.25 2.7,2.25, height 0.25
TJA1049T_3J-Footprint-1 [mm]
  rrect50% 1.45x0.6 smd: 1(-2.725,1.905) 2(-2.725,0.635) 3(-2.725,-0.635) 4(-2.725,-1.905) 5(2.725,-1.905) 6(2.725,-0.635) 7(2.725,0.635) 8(2.725,1.905)
  silkscreen extent -2.84,2.62 -2.74,2.72, body extent -3,-2.5 3,2.5, height 1.75
TP-1.00MM [mm]
  rrect100% 1x1 smd paste-2.54: X(0,0)
"TRJK0071AWNL -Footprint-2" [mm]
  round 1.6 hole 0.9: 1(5.075,0) 2(3.045,0) 3(1.015,0) 4(-1.015,0) 5(-3.045,0) 6(-5.075,0) 7(6.09,2.54) 8(4.06,2.54) 9(2.03,2.54) 10(-2.03,2.54) 11(-4.06,2.54) 12(-6.09,2.54) 13(7.51,-12.95) 14(7.51,-15.49) 15(-7.51,-10.41) 16(-7.51,-12.95) 17(-7.51,-15.49)
  round 2.2 hole 1.6: SH1(-8.78,-6.6) SH2(8.78,-6.6)
  round 0 hole 3.25 unplated: SHNP1(-4.825,-6.6) SHNP2(4.825,-6.6)
  body extent -10.45,-19.78 10.5,4.35, height 12.89
USB-A-S-RA-CS11-SMT-HF-TR [mm]
  rrect25% 1.45x3 smd paste+0 mask+0.05: 1(-3.5,6) 2(-1,6) 3(1,6) 4(3.5,6)
  oval 1.8x3 hole 0.8 slot 1.6 at 90 deg paste-2539.97 mask+0.05: SHIELD1(-6.525,3.5) SHIELD2(6.525,3.5)
  oval 1.8x4 hole 0.8 slot 2.8 at 90 deg copper offset 0,0.2 paste-2539.97 mask+0.05: SHIELD3(-7.025,-3.4) SHIELD4(7.025,-3.4)
  body extent -7.25,-8.25 7.25,6.42, height 7.72

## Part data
C1 C2 C3 C4: library part C0097-A.11, "CAP CHIP 0402 47pF 5% 25V C0G", Case Code (Imperial)=0402, Dielectric=C0G, Manufacturer=Yageo, Tolerance=5%, Voltage=25V
C5 C9 C10 C21 C22 C28 C29 C30 C31: library part C0043-A.14, "CAP CHIP 0603 100nF 10% 50V X7R", Case Code (Imperial)=0603, Dielectric=X7R, Manufacturer=Walsin, Manufacturer 2=Hottech, Manufacturer 3="Samsung Electro-Mechanics", Part number 2=C1608B104K500NT, Part number 3=CL10B104KB8NNNC, Tolerance=10%, Voltage=50V
C6 C7 C8 C13 C14 C15 C16: library part C0098-A.12, "CAP CHIP 0603 47uF 20% 6.3V X5R", Case Code (Imperial)=0603, Dielectric=X5R, Manufacturer=Murata, Tolerance=20%, Voltage=6.3V
C11 C12 C23 C24 C25 C26: library part C0111-A.7, "CAP CHIP 0805 22uF 20% 25V X5R", Case Code (Imperial)=0805, Dielectric=X5R, Manufacturer="Samsung Electro-Mechanics", Tolerance=20%, Voltage=25V
C17 C19 C20: library part C0009-A.15, "CAP CHIP 0402 10nF 10% 50V X7R", Case Code (Imperial)=0402, Dielectric=X7R, Manufacturer=Hottech, Manufacturer 2="Murata Electronics", Manufacturer 3=YAGEO, Part number 2=CC0402KRX7R9BB103, Tolerance=10%, Voltage=50V
C18: library part C0074-A.12, "CAP CHIP 0402 150pF 1% 50V C0G", Case Code (Imperial)=0402, Dielectric=C0G, Manufacturer=Murata, Tolerance=1%, Voltage=50V
C27: library part C0059-A.14, "CAP CHIP 0805 4.7nF 10% 1000V X7R", Case Code (Imperial)=0805, Dielectric=X7R, Manufacturer="PSA Shenzen", Manufacturer 2=KEMET, Part number 2=C0805V472KDRACTU, Part number 3=C0805C472KDRACTU, Tolerance=10%, Voltage=1kV
D1 D2 D3 D4: library part D0027-A.4, "DIODE TVS SMD 0402 14V 40V", Manufacturer="Littelfuse Inc"
D5: library part D0025-A.5, "TVS ARRAY 4LIN.8kV 1pF SOT143B", Manufacturer=Nexperia
ETH_L1 ETH_L2 PCIE_CLKREQ1 USB1 USB2 USB3 USB4 VSYS1: library part UT0013-A.6, Manufacturer="This is not a component"
Fiducial_1 Fiducial_2: library part UT0024-A.6
H1 H2 H3 H4: library part S0041-A.4, "RND STANDOFF M2.5X0.45 no paste no metalization in hole", Manufacturer="Wurth Elektronik", Part Number=9774070151R
J1: library part J0155-A.6, "CONN RCPT FEMALE D80POS 0.4MM SMD GOLD", Current Rating=300mA, Manufacturer=Hirose, Package Quantity=1, Part Number=DF40HC(4.0)-80DS-0.4V(51), Voltage Rating=30V
J2: library part J0156-A.5, "CONN RCPT FEMALE D80POS 0.4MM SMD GOLD", Current Rating=300mA, Manufacturer=Hirose, Package Quantity=1, Part Number=DF40HC(4.0)-80DS-0.4V(51), Voltage Rating=30V
J3: library part J0068-A.9, "CONN CONN STRIP THD 1,27 M/2/D 10v AuF H6,3 JTAG", Manufacturer="Adam Tech"
J4: library part J0319-A.4, "CONN SCREW TERMINAL 22TW-277 6 PIN BLACK", Manufacturer="4U CON", Max Current Rating=10A
J5: library part J0297-A.4, "CONN BATT COINCELL SMD CR1225", Manufacturer="Keystone Electronics"
J6 J7: library part J0379-A.2, "Turret Connector TH 5,56mm lenght", Manufacturer="Keystone Electronics"
J8: library part J0186-A.8, "CONN PCI EXP MINI FEMALE 52POS Center board heigth 7.95mm", Flammability Rating="UL94 V-0", High Temperature Housing=Yes, Housing Color=Black, Manufacturer="TE Connectivity", Package Quantity=500
J9: library part J0004-A.5, "CONN Header Through Hole 6 position 0.100\" (2.54mm)", Manufacturer="Adam Tech"
J10: library part J0320-A.3, "CONN FFC/FPC Connector, 15 Contact(s), 1 Row(s), TOP CONTACT, Female, Right Angle, 1mm Pitch, Locking ZIF", Contact Resistance=10mR, Flammability Rating="UL94 V-0", Insulation Color=Natural, Insulation Resistance=1GR, Manufacturer="TE Connectivity", Max Operating Temperature=85°C, Min Operating Temperature=-40°C
J11: library part J0249-A.9, "CONN SOCKET 2ROW 20POS VERTICAL PASS THROUGH + SMD with fixing + pick and place cap, in reel", Manufacturer=4UCON
J12: library part J0011-A.5, "CONN Micro SD", Manufacturer=Amphenol
J13: library part J0329-A.9, "CONN USB A 2.0 FEMALE RIGHT ANGLE SMD + TH TAPE AND REEL", Manufacturer="Adam Tech"
J14 J15: library part J0356-A.7, "HEADER TH 2.54mm VERT. MALE 2x22POS", Manufacturer="Wurth Elektronik", Manufacturer 2="Adam Tech", Part number 2=PH2-44-UA
J16: library part J0434-A.3, "CONN. HEADER TH 2.54mm VERT. MALE 2x14POS", Manufacturer="Adam Tech"
J17: library part J0390-A.5, "CONN. HEADER TH 2.54mm VERT. MALE 1x5 POS", Manufacturer="Adam Tech"
J18: library part J0027-A.7, "CONN ETHERNET 1GIGABIT", Manufacturer=TRXCOM
J19: library part J0265-A.9, "CONN SOCKET 2ROW 24POS VERTICAL PASS THROUGH + SMD with fixing + reel + cap for pick and place", Manufacturer=4UCON
L1: library part I0049-A.6, "IND FIXED SMD 3.3UH 3.5A 76 mOHM", Current=4A, DC Resistance (DCR)=76mR, Inductance=3.3µH, Manufacturer=Bourns, Max Operating Temperature=150°C, Min Operating Temperature=-40°C, Test Frequency=100kHz, Tolerance=20%
PB1: library part B0001-A.7, "PUSHBUTTON WHITE NO ANCHORS", Color=White, Manufacturer=Switronic
R1 R2 R6: library part R0210-A.19, "RES CHIP 0402 5k1 1% 1/16W", Case Code (Imperial)=0402, Manufacturer=YAGEO, Power=62.5mW, Temperature coefficient=100ppm, Tolerance=1%
R3 R11 R21: library part R0096-A.22, "RES CHIP 0603 0R 1/10W", Case Code (Imperial)=0603, Manufacturer=Vishay, Power=100mW, Temperature coefficient=0ppm, Tolerance=0%
R4: library part R0046-A.26, "RES CHIP 0402 49R9 1% 1/16W", Case Code (Imperial)=0402, Manufacturer=Vishay, Power=62.5mW, Temperature coefficient=200ppm, Tolerance=1%
R5 R18 R20: library part R0003-A.24, "RES CHIP 0402 10k 1% 1/16W", Case Code (Imperial)=0402, Manufacturer=Vishay, Power=62.5mW, Temperature coefficient=100ppm, Tolerance=1%
R7: library part R0037-A.26, "RES CHIP 0402 75k 1% 1/16W", Case Code (Imperial)=0402, Manufacturer=YAGEO, Power=62.5mW, Temperature coefficient=100ppm, Tolerance=1%
R8 R13 R14 R15 R16: library part R0020-A.24, "RES CHIP 0402 3k3 1% 1/16W", Case Code (Imperial)=0402, Manufacturer=YAGEO, Power=62.5mW, Temperature coefficient=200ppm, Tolerance=1%
R9: library part R0172-A.26, "RES CHIP 0402 34k 1% 1/16W", Case Code (Imperial)=0402, Manufacturer=YAGEO, Power=62.5mW, Temperature coefficient=200ppm, Tolerance=1%
R10: library part R0098-A.22, "RES CHIP 0603 75k 1% 1/10W", Case Code (Imperial)=0603, Manufacturer=Vishay, Power=100mW, Temperature coefficient=100ppm, Tolerance=1%
R12: library part R0163-A.20, "RES CHIP 0603 1M 1% 1/10W", Case Code (Imperial)=0603, Manufacturer=Vishay, Power=100mW, Temperature coefficient=100ppm, Tolerance=1%
R17 R19: library part R0055-A.25, "RES CHIP 0402 470R 5% 1/16W", Case Code (Imperial)=0402, Manufacturer=Vishay, Power=62.5mW, Temperature coefficient=200ppm, Tolerance=5%
SIM1: library part J0300-A.1, "CONN SIM NANO HINGED WITH SWITCH, 6P, 1.40MM PROF", Manufacturer=GCT
SW1 SW2: library part S0022-A.4, "SWITCH DIP NORMALLY OPEN", Contact Resistance=100mR, Current Rating=25mA, Manufacturer="CTS Corporation", Max Operating Temperature=85°C, Max Voltage Rating (DC)=24V, Min Operating Temperature=-55°C, Package Quantity=145
SW3: library part S0033-A.1, "SWITCH DIP 4 positions NORMALLY OPEN", Contact Resistance=100mR, Current Rating=25mA, Manufacturer="CTS Corporation", Max Operating Temperature=85°C, Max Voltage Rating (DC)=24V, Min Operating Temperature=-55°C
U1: library part U0092-A.9, "IC REG BUCK ADJ 6A SYNC 14VQFN", Manufacturer="Texas Instruments"
U2: library part U0114-A.7, "IC CAN TRANSCEIVER 1Mbps STBY 5.25V SOIC8", Manufacturer=NXP

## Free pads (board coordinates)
  round 1 hole 2.7 unplated paste-2539.97 mask+2.5: FIXING(20,35) FIXING(20,66) FIXING(54.8,78.7) FIXING(95,18)

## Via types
v1: diameter 0.6, hole 0.3, TOP to BOTTOM, tented both sides, 522 vias

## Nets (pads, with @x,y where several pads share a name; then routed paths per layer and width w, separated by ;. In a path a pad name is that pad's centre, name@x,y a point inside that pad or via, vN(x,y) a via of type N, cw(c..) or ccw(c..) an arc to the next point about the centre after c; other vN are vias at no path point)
+3V3_BUCK: C13.2 C14.2 C15.2 C16.2 J9.3 L1.2 R4.2 | length 13
  TOP w0.3: v1(78.155,45.013) R4.2@78.155,46.096
  BOTTOM w0.5: v1(78.155,45.013) 83.132,45.013 88.025,49.906 v1(88.025,49.92)
+3V3_PCIE: C6.2 C7.2 C8.2 C9.1 J8.2 J8.24 J8.39 J8.41 J8.52 J9.1 | length 15.5
  TOP w0.4: J8.41@68.256,69.55 68.256,70.71 C9.1@69.046,71.5 ; J8.39@69.056,69.55 69.046,69.56 C9.1@69.046,71.5 ; v1(69.059,72.458) 69.059,71.513 C9.1@69.046,71.5
  TOP w0.5: v1(62.979,62.895) 63.41,62.895 63.856,62.45 J8.52@63.856,61.35 ; C8.2@63.881,59.201 J8.52@63.881,61.314 ; J8.24@75.056,61.35 C7.2@75.056,59.304 v1(75.96,59.305) ; v1(86.163,59.176) C6.2@87.076,59.176 87.076,61.329 J8.2@87.056,61.35 J8.2@87.059,61.353
CAM.CK_1_N: J2.20 J10.8 J11.7 | length 49.4
  TOP w0.15: 33.9,56.373 J2.20@33.9,58.96
  TOP w0.2: v1(32.62,68.851) 32.656,68.851 32.921,68.586 33.386,68.586 34.085,69.285 34.085,70.231 J11.7@34.29,70.435 ; J10.8@38.1,80.6 38.1,79.905 38.4,79.605 38.4,79.239 v1(38.104,78.942)
  TOP w0.25: v1(29.356,52.543) 29.879,52.543 29.956,52.466 30.414,52.466 30.609,52.27 32.672,52.27 33.9,53.498 33.9,56.373
  SIG w0.15: v1(29.356,52.543) 29.356,53.607 29.127,53.837 29.127,65.784 32.193,68.851 32.711,68.851 32.964,68.598 35.794,68.598 36.722,69.527 37.885,69.527 38.323,69.964 38.323,75.54 38.531,75.748 38.531,77.877 38.065,78.342 38.065,78.904 v1(38.104,78.942)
